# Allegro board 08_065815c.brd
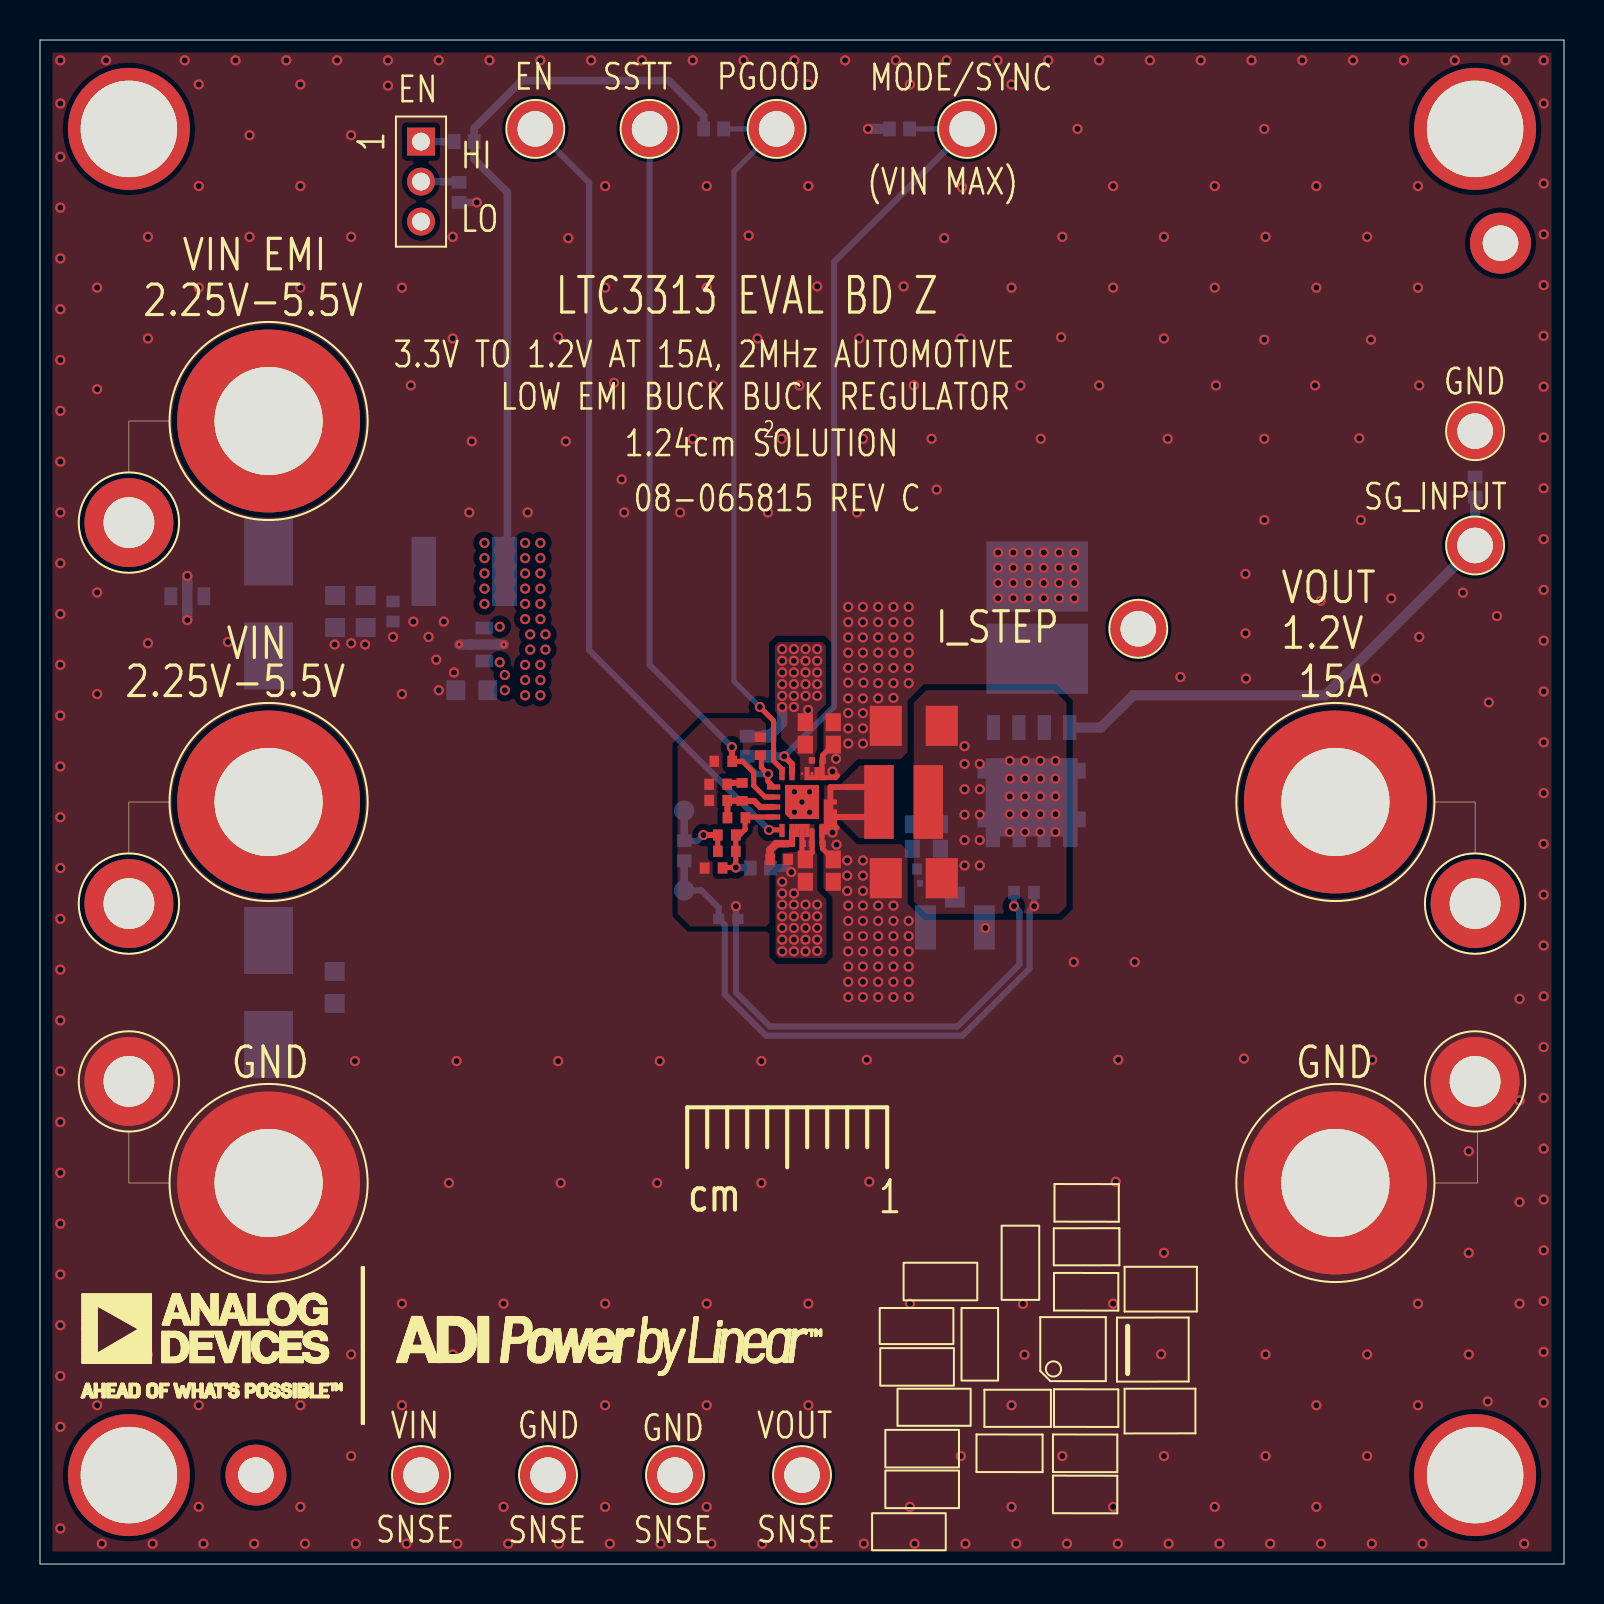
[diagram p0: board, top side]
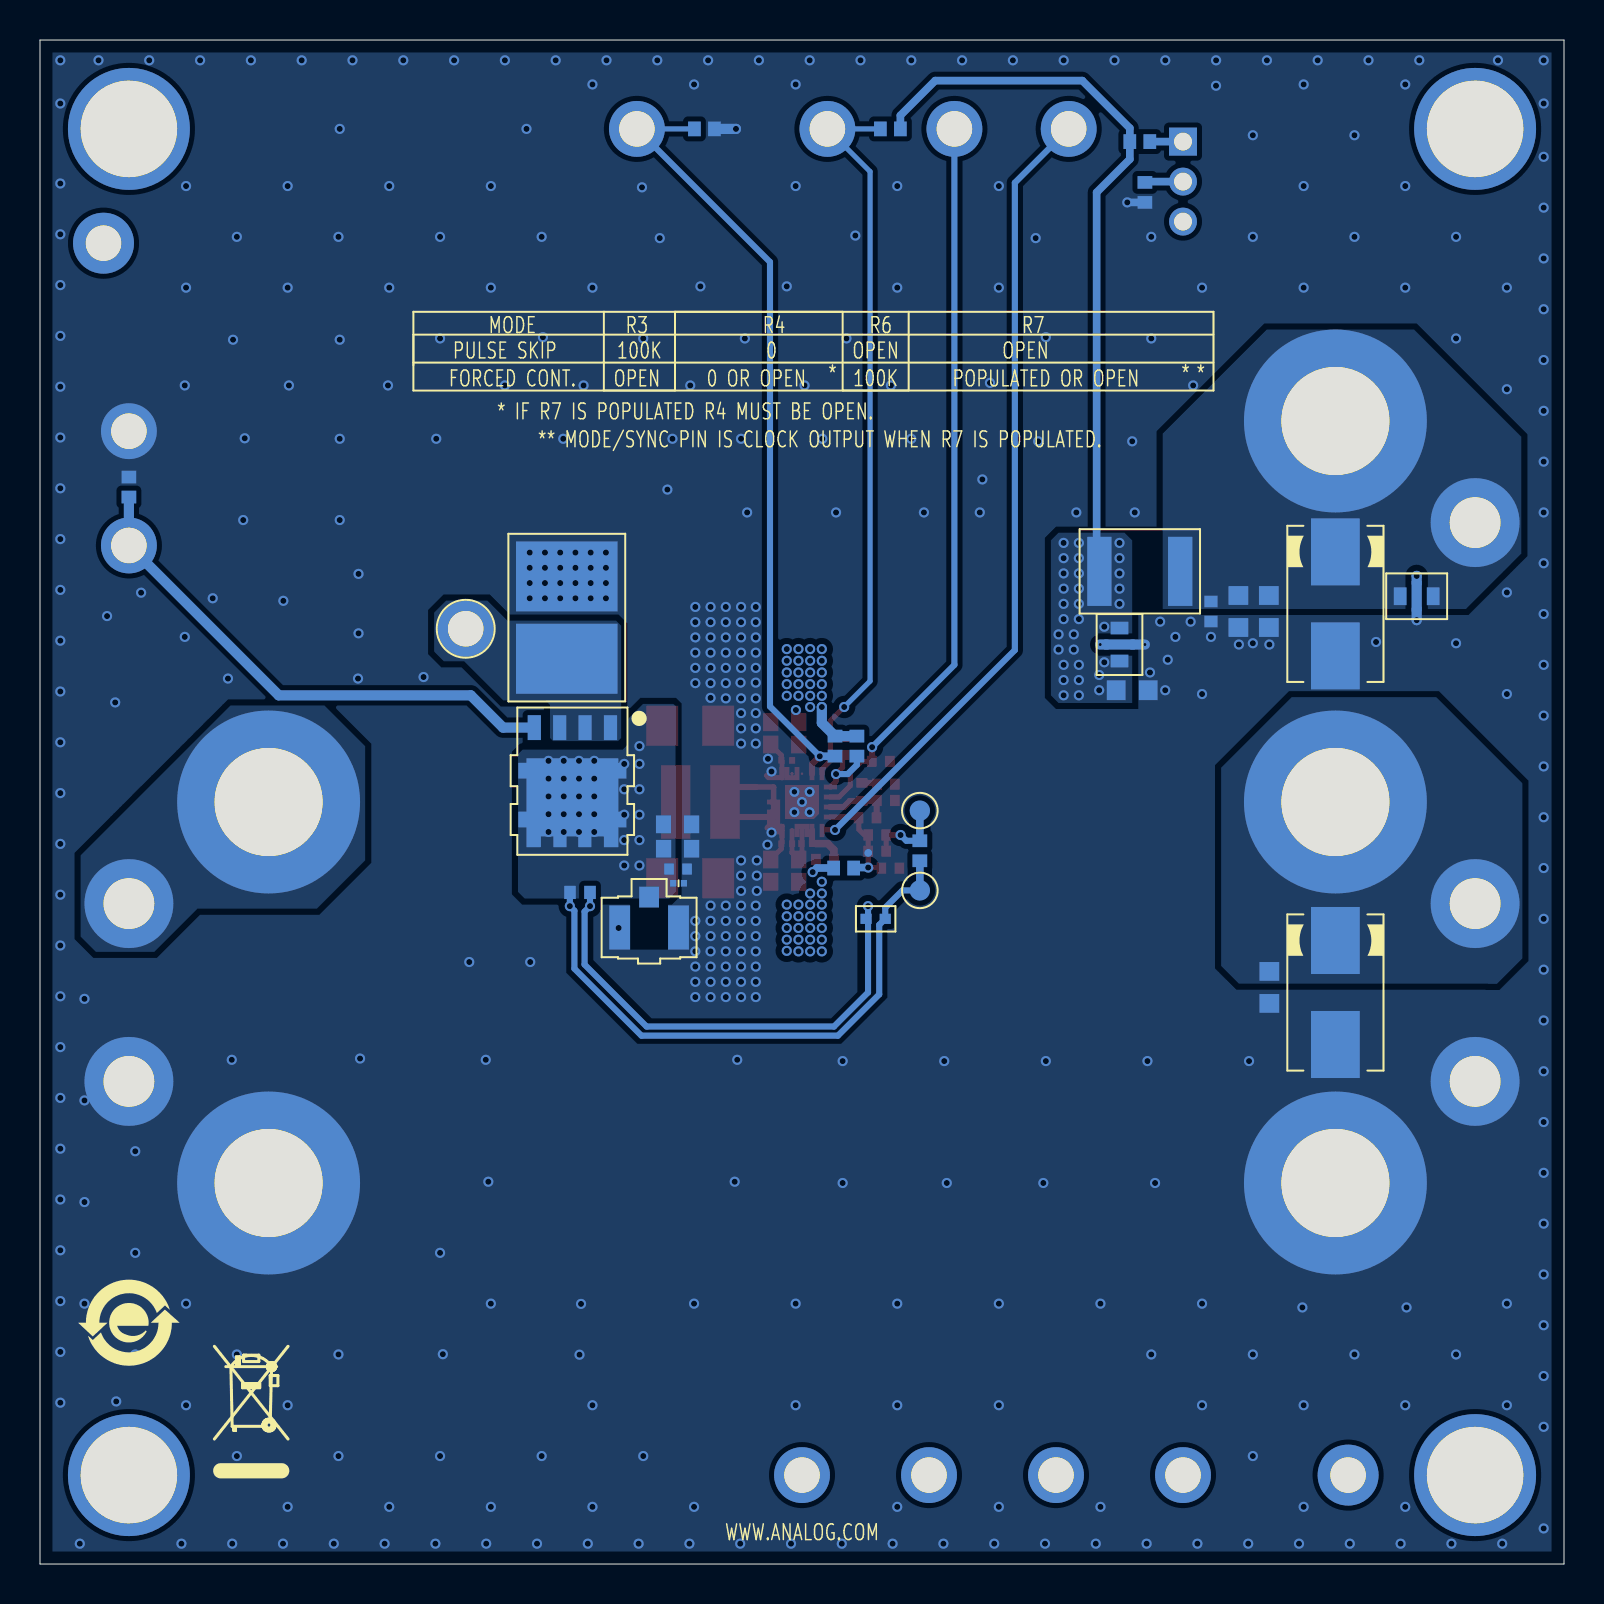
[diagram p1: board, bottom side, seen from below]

Outline 76.2 x 76.2 mm; copper layers: TOP, INTERNAL LAYER 1, INTERNAL LAYER 2, BOTTOM. Coordinates in mm from the lower left corner of the outline.
Outline path: 0,76.2 0,0 76.2,0 76.2,76.2 0,76.2

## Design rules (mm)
constraint set DEFAULT: min track width 0.203
net group SENSE LINES: nets GND_POWER

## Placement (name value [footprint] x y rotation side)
C1  470uF  [C7343-43]  11.43 28.57 270 bottom
C2  10UF  [C0603]  38.96 35.23 180 top
C3  10UF  [C0603]  38.96 40.97 180 top
C4  47pF  [C0402]  34.34 36.45 180 top
C5  47UF  [C1206H71]  43.69 41.91 0 top
C6  47UF  [C1206H71]  43.69 34.29 0 top
C7  0.1uF  [C0402]  49.2 33.58 180 bottom
C8  1UF  [C0201]  44.27 34.04 0 bottom
C9  0.033uF  [C0402]  34.16 40.13 0 top
C10  3.3pF  [C0402]  33.91 38.18 0 top
C11  0.1uF  [C0402H22]  34.42 32.26 180 bottom
C12  2.2UF  [C0402]  36.96 35.23 180 top
C13  10uF  [C0603#2]  16.28 47.62 90 bottom
C14  10uF  [C0603#2]  21.59 43.69 0 bottom
C15  0.1uF  [C0402]  17.65 47.62 90 bottom
C16  10uF  [C0603#2]  14.73 28.83 90 bottom
C17  10uF  [C0603#2]  14.76 47.62 90 bottom
C18  470uF  [C7343-43]  11.43 48.01 270 bottom
C19  1UF  [C0201]  38.86 36.02 180 top
C20  1UF  [C0201]  38.86 40.18 180 top
C21  10UF  [C0603]  38.96 34.11 180 top
C22  10UF  [C0603]  38.96 42.09 180 top
C23  0.1uF  [C0201]  37.87 36.02 0 top
C24  470pF  [C0402]  33.91 38.99 0 top
C25  0.22UF  [C0603-4P]  7.37 48.39 180 bottom
C26  0.22UF  [C0603-4P]  22.23 45.97 270 bottom
C27  10UF  [C0603]  44.32 36.98 0 bottom
C28  10UF  [C0603]  44.32 35.76 0 bottom
C29  2.2UF  [C0402]  44.3 34.75 180 bottom
J1  U.FL-R-SMT-1(01)  [CNHIROSE-U_FL-R-SMT-1]  45.75 31.83 0 bottom
JP1  62000311121  [CNTHMHDR1X3L236W79H244]  19.05 71.12 270 top
L1  0.08UH  [LSMSQ157H83]  43.18 38.1 0 top
L2  100OHM AT 100MEGHZ  [L1812H100]  21.21 49.63 0 bottom
NOREF  -  []  -6.46 -76.8 0 top
NOREF#2  -  [unnamed#2]  4.45 71.75 0 top
NOREF#3  -  []  76.2 0 90 top
NOREF#4  -  []  573.08 -141.72 0 top
NOREF#5  -  [unnamed#2]  4.45 4.45 0 top
NOREF#6  -  []  253.15 176.72 0 top
NOREF#7  -  []  76.2 76.2 180 top
NOREF#8  -  []  548.13 -131.57 0 top
NOREF#9  -  []  32.36 22.83 0 top
NOREF#10  -  []  287.87 -23.16 0 top
NOREF#11  -  []  -142.37 -122.3 0 top
NOREF#12  -  [unnamed#2]  71.75 71.75 0 top
NOREF#13  -  []  574.58 -131.56 0 top
NOREF#14  -  []  -184.91 -324.23 0 top
NOREF#15  -  []  -29.02 -64.83 0 top
NOREF#16  -  []  2.08 7.03 0 top
NOREF#17  -  []  605.28 -136.65 0 top
NOREF#18  -  []  38.1 86.36 0 top
NOREF#19  -  []  371.82 -130.71 0 top
NOREF#20  -  []  367.58 -140.87 0 top
NOREF#21  -  []  402.32 -135.81 0 top
NOREF#22  -  []  0 76.2 270 top
NOREF#23  -  [unnamed#2]  73.03 66.04 0 top
NOREF#24  -  []  76.2 0 90 top
NOREF#25  -  []  345.17 -130.73 0 top
NOREF#26  -  [unnamed#2]  71.75 4.45 0 top
NOREF#27  -  []  -114.3 -114.3 0 top
NOREF#28  -  []  -184.91 -324.23 0 top
NOREF#29  -  [unnamed#2]  10.79 4.45 0 top
NOREF#30  -  []  71.75 12.06 180 bottom
NOREF#31  -  []  65.84 4.34 180 bottom
Q1  BSC010NE2LSIATMA1  [POWERFLAT_5X6]  49.58 39.14 0 bottom
R1  1MEG  [R0402]  21.21 71.12 0 bottom
R2  249K  [R0402]  20.95 68.58 270 bottom
R3  100K  [R0402]  36.45 40.89 90 bottom
R4  0  [R0402]  35.36 40.89 90 bottom
R5  100K  [R0402]  36.02 34.8 0 bottom
R6  100K  [R0402]  42.98 71.75 0 bottom
R7  100K  [R0402]  36.02 40.89 270 top
R8  20  [R0402]  32.21 35.66 90 bottom
R9  140K  [R0402]  34.34 35.64 180 top
R10  100K  [R0402]  33.68 34.8 0 top
R11  100K  [R0402]  33.68 71.75 0 bottom
R12  4.99K  [R0402]  35.1 38.61 90 top
R13  100K  [R0402]  34.82 37.31 0 top
R14  0.02  [R2818]  49.86 47.32 270 bottom
R15  10K  [R0402]  71.75 53.85 270 bottom
TP1  2308-2-00-80-00-00-07-0  [CNMILLMAX2308]  46.35 71.75 0 top
TP2  2308-2-00-80-00-00-07-0  [CNMILLMAX2308]  71.75 56.64 0 top
TP3  2308-2-00-80-00-00-07-0  [CNMILLMAX2308]  19.05 4.45 0 top
TP4  2501-2-00-80-00-00-07-0  [CNMILLMAX2501]  4.45 33.02 0 top
TP5  2308-2-00-80-00-00-07-0  [CNMILLMAX2308]  38.1 4.45 0 top
TP6  575-4  [CNBANANAD312LD203]  11.43 38.1 0 top
TP7  2501-2-00-80-00-00-07-0  [CNMILLMAX2501]  71.75 33.02 0 top
TP8  575-4  [CNBANANAD312LD203]  64.77 38.1 0 top
TP9  575-4  [CNBANANAD312LD203]  11.43 19.05 0 top
TP10  2501-2-00-80-00-00-07-0  [CNMILLMAX2501]  4.45 24.13 0 top
TP11  575-4  [CNBANANAD312LD203]  64.77 19.05 0 top
TP12  2308-2-00-80-00-00-07-0  [CNMILLMAX2308]  25.4 4.45 0 top
TP13  2501-2-00-80-00-00-07-0  [CNMILLMAX2501]  71.75 24.13 0 top
TP14  2308-2-00-80-00-00-07-0  [CNMILLMAX2308]  31.75 4.45 0 top
TP15  2308-2-00-80-00-00-07-0  [CNMILLMAX2308]  24.77 71.75 0 top
TP16  2308-2-00-80-00-00-07-0  [CNMILLMAX2308]  30.48 71.75 0 top
TP17  2308-2-00-80-00-00-07-0  [CNMILLMAX2308]  36.83 71.75 0 top
TP18  2501-2-00-80-00-00-07-0  [CNMILLMAX2501]  4.45 52.07 0 top
TP19  575-4  [CNBANANAD312LD203]  11.43 57.15 0 top
TP20  2308-2-00-80-00-00-07-0  [CNMILLMAX2308]  71.75 50.93 0 top
TP21  2308-2-00-80-00-00-07-0  [CNMILLMAX2308]  54.91 46.76 0 top
TPA1  TESTPAD  [TPSMC40]  32.21 37.67 180 bottom
TPB1  TESTPAD  [TPSMC40]  32.21 33.68 180 bottom
U1  LTC3313EV  [QFN18_3X3_PAD1_7X1_7_RP]  38.1 38.1 0 top

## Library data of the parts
C1 C18 = CAPP: Tolerance: 20; User Part Number: UPN; alternate symbols: (); part number: CAPP_SM-470UF,6.3V,20,E041192,C7343-43; tolerance: 20
C2 C3 C21 C22 C27 C28 = CAP: User Part Number: UPN; Tolerance: 20; alternate symbols: (C0603L); part number: CAP_SM-10UF,6.3V,20,E044636,C0603; tolerance: 20
C4 = CAP: User Part Number: UPN; Tolerance: 5; alternate symbols: (C0402L); part number: CAP_SM-47PF,50V,5,E011821,C0402; tolerance: 5
C5 C6 = CAP: Tolerance: 20; User Part Number: UPN; alternate symbols: (); part number: CAP_SM-47UF,6.3V,20,E044689,C1206H71; tolerance: 20
C7 C15 = CAP: User Part Number: UPN; Tolerance: 10; alternate symbols: (C0402L); part number: CAP_SM-0.1UF,16V,10,E028141,C0402; tolerance: 10
C8 C19 C20 = CAP: Tolerance: 20; User Part Number: UPN; alternate symbols: (C0201L); part number: CAP_SM-1UF,6.3V,20,E044778,C0201; tolerance: 20
C9 = CAP: User Part Number: UPN; Tolerance: 10; alternate symbols: (C0402L); part number: CAP_SM-0.033UF,25V,10,E025701,C0402; tolerance: 10
C10 = CAP: User Part Number: UPN; Tolerance: 0.1pF; alternate symbols: (C0402L); part number: CAP_SM-3.3PF,50V,0.1PF,E041182,C0402; tolerance: 0.1pF
C11 = CAP: Tolerance: 10; User Part Number: UPN; alternate symbols: (); part number: CAP_SM-0.1UF,50V,10,E018452,C0402H22; tolerance: 10
C12 C29 = CAP: User Part Number: UPN; Tolerance: 10; alternate symbols: (C0402L); part number: CAP_SM-2.2UF,10V,10,E055500,C0402; tolerance: 10
C13 C14 C16 C17 = CAP: User Part Number: UPN; Tolerance: 20; alternate symbols: (C0603L,C0603L_ALT); part number: CAP_SM-10UF,6.3V,20,E030255,C0603; tolerance: 20
C23 = CAP: Tolerance: 10; User Part Number: UPN; alternate symbols: (C0201NC,C0201L); part number: CAP_SM-0.1UF,10V,10,E033924,C0201; tolerance: 10
C24 = CAP: User Part Number: UPN; Tolerance: 5; alternate symbols: (C0402L); part number: CAP_SM-470PF,50V,5,E021713,C0402; tolerance: 5
C25 C26 = CAP4P_V2: Tolerance: 20; User Part Number: UPN; alternate symbols: (); part number: CAP4P_V2_SM-0.22UF,6.3V,20,E043922,C0603-4P; tolerance: 20
J1 = CNBNC3P: Tolerance: N/A; User Part Number: UPN; alternate symbols: (); part number: CNBNC3P_SM-U.FL-R-SMT-1(01),E022198,CNHIROSE-U_FL-R-SMT-1; tolerance: N/A
JP1 = CN3P: User Part Number: UPN; Tolerance: N/A; alternate symbols: (); part number: CN3P_TH-62000311121,E033291,CNTHMHDR1X3L236W79H244; tolerance: N/A
L1 = IND: User Part Number: UPN; Tolerance: 20; alternate symbols: (); part number: IND_SM-0.08UH,20,E050319,LSMSQ157H83; tolerance: 20
L2 = FERRITE: User Part Number: UPN; Tolerance: 25; alternate symbols: (); part number: FERRITE_SM-100OHM AT 100MEGHZ,25,E032797,L1812H100; tolerance: 25
Q1 = TRANNMOSFET_V13: User Part Number: UPN; Tolerance: N/A; alternate symbols: (); part number: TRANNMOSFET_V13_SM-BSC010NE2LSIATMA1,E051623,POWERFLAT_5X6; tolerance: N/A
R1 = RES: User Part Number: UPN; Tolerance: 1; alternate symbols: (R0402L); part number: RES_SM-1MEG,E041482,1/16W,1,R0402; tolerance: 1
R2 = RES: User Part Number: UPN; Tolerance: 1; alternate symbols: (R0402L); part number: RES_SM-249K,E041500,1/16W,1,R0402; tolerance: 1
R3 R5-R7 R10 R13 = RES: User Part Number: UPN; Tolerance: 1; alternate symbols: (R0402L,R0402L_ALT); part number: RES_SM-100K,E003796,1/10W,1,R0402; tolerance: 1
R4 = RESJMPRSHRT: User Part Number: UPN; Tolerance: JUMPER; alternate symbols: (R0402L); part number: RESJMPRSHRT_SM-0,E003438,1/10W,JUMPER,R0402; tolerance: JUMPER
R8 = RES: User Part Number: UPN; Tolerance: 1; alternate symbols: (R0402L); part number: RES_SM-20,E020520,1/10W,1,R0402; tolerance: 1
R9 = RES: User Part Number: UPN; Tolerance: 1; alternate symbols: (R0402L); part number: RES_SM-140K,E045852,1/16W,1,R0402; tolerance: 1
R11 = RES: User Part Number: UPN; Tolerance: 5; alternate symbols: (R0402L); part number: RES_SM-100K,E027220,1/16W,5,R0402; tolerance: 5
R12 = RES: User Part Number: UPN; Tolerance: 1; alternate symbols: (R0402L); part number: RES_SM-4.99K,E006643,1/10W,1,R0402; tolerance: 1
R14 = RES: Tolerance: 1; User Part Number: UPN; alternate symbols: (); part number: RES_SM-0.02,E045144,10W,1,R2818; tolerance: 1
R15 = RES: User Part Number: UPN; Tolerance: 5; alternate symbols: (R0402L); part number: RES_SM-10K,E019640,1/16W,5,R0402; tolerance: 5
TP1-TP3 TP5 TP12 TP14-TP17 TP20 TP21 = CNTP1P: User Part Number: UPN; Tolerance: N/A; alternate symbols: (); part number: CNTP1P_TH-2308-2-00-80-00-00-07-0,E030692,CNMILLMAX2308; tolerance: N/A
TP4 TP7 TP10 TP13 TP18 = CNTP1P: User Part Number: UPN; Tolerance: N/A; alternate symbols: (); part number: CNTP1P_TH-2501-2-00-80-00-00-07-0,E031108,CNMILLMAX2501; tolerance: N/A
TP6 TP8 TP9 TP11 TP19 = CNTP1P: Tolerance: N/A; User Part Number: UPN; alternate symbols: (); part number: CNTP1P_TH-575-4,E012555,CNBANANAD312LD203; tolerance: N/A
TPA1 TPB1 = NCTESTPAD: Tolerance: N/A; User Part Number: UPN; alternate symbols: (); part number: NCTESTPAD_SM-TESTPAD,E019801,TPSMC40; tolerance: N/A
U1 = ADLTC3313: User Part Number: UPN; Tolerance: N/A; alternate symbols: (); part number: ADLTC3313_SM-LTC3313EV,E046094,QFN18_3X3_PAD1_7X1_7_RP; tolerance: N/A

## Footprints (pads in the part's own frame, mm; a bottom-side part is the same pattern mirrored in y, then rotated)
C0201
  rect 0.305x0.33 smd: 1(-0.27,0) 2(0.27,0)
C0402
  rect 0.483x0.559 smd: 1(-0.45,0) 2(0.45,0)
C0402H22
  rect 0.559x0.508 smd: 1(-0.479,0) 2(0.479,0)
C0603
  rect 0.762x0.889 smd: 1(-0.7,0) 2(0.7,0)
C0603#2
  rect 0.94x0.991 smd: 1(-0.8,0) 2(0.8,0)
C0603-4P
  rect 0.635x0.889 smd: 1(-0.826,0) 3(0.826,0)
  round 0.127 smd: 2(0,-0.635) 4(0,0.635)
C1206H71
  rect 1.6x2.007 smd: 1(-1.397,0) 2(1.397,0)
C7343-43
  rect 3.353x2.438 smd: N(2.6,0) P(-2.6,0)
CNBANANAD312LD203
  round 9.144 hole 5.41: 1(0,0)
CNHIROSE-U_FL-R-SMT-1
  rect 0.991x1.041 smd: 1(0,-1.521)
  rect 1.041x2.21 smd: 2(-1.471,0) 3(1.471,0)
CNMILLMAX2308
  round 2.794 hole 1.778: 1(0,0)
CNMILLMAX2501
  round 4.445 hole 2.54: 1(0,0)
CNTHMHDR1X3L236W79H244
  rect 1.397x1.397 hole 0.889: 1(0,0)
  round 1.397 hole 0.889: 2(2,0) 3(4,0)
L1812H100
  rect 1.219x3.454 smd: 1(-2.02,0) 2(2.02,0)
LSMSQ157H83
  rect 1.473x3.683 smd: 1(-1.232,0) 2(1.232,0)
POWERFLAT_5X6
  rect 0.66x1.245 smd: 1(-1.905,-2.678) 2(-0.635,-2.678) 3(0.635,-2.678) 4(1.905,-2.678)
  custom 1.111x1.111 smd: 5(0,1.077)
QFN18_3X3_PAD1_7X1_7_RP
  rect 0.254x0.66 smd: 1(-1,-1.425) 2(-0.5,-1.425) 5(1,-1.425) 10(1,1.42) 13(-0.5,1.42) 14(-1,1.42)
  custom 0.165x0.165 smd: 3(0,-1.425) 6(1.42,-0.75) 11(0.5,1.42)
  round 0.127 smd: 4(0.5,-1.425) 7(1.42,-0.25) 8(1.42,0.25) 9(1.42,0.75) 12(0,1.42)
  rect 0.66x0.254 smd: 15(-1.42,0.75) 16(-1.42,0.25) 17(-1.42,-0.25) 18(-1.42,-0.75)
  custom 0.425x0.425 smd: PAD(0,0)
R0402
  rect 0.483x0.559 smd: 1(-0.45,0) 2(0.45,0)
R2818
  rect 3.505x5.08 smd: 1(-2.057,0) 2(2.057,0)
TPSMC40
  round 1.016 smd: 1(0,0)
unnamed#2
  round 6.096 hole 4.826 unplated: (0,0)

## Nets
GND_POWER: C1.N(N2) C2.1 C3.1 C5.1 C6.1 C7.2(N2) C8.1 C9.1 C10.1 C11.1 C12.2(N2) C13.1 C14.1 C15.1 C16.1 C17.1 C18.N(N2) C19.1 C20.1 C21.1 C22.1 C23.1 C24.1 C25.2 C25.4(G2) C26.2 C26.4(G2) C27.1 C28.1 C29.2(N2) J1.2 J1.3(SH2) R2.2(N2) R6.1 R7.1 R10.1 R14.1 R15.1 TP2.1(N1) TP9.1(N1) TP10.1(N1) TP11.1(N1) TP12.1(N1) TP13.1(N1) TP14.1(N1) U1.2 U1.5 U1.10 U1.PAD
VIN: C1.P C2.2(N2) C3.2(N2) C12.1 C14.2(N2) C16.2(N2) C19.2(N2) C20.2(N2) C21.2(N2) C22.2(N2) C23.2(N2) C26.1 C26.3 L2.2(N2) R1.2(N2) R3.2(N2) R4.2(S2) R5.2(N2) R11.1 TP3.1(N1) TP4.1(N1) TP6.1(N1) U1.3 U1.4 U1.11 U1.12(VIN_4)
EN: JP1.2 R2.1 TP15.1(N1) U1.1
ITH: C10.2(N2) R12.1 R13.1 U1.17
MODE: R3.1 R6.2(N2) TP1.1(N1) U1.13
PGOOD: R11.2(N2) TP17.1(N1) U1.14
RT: R4.1 R7.2(N2) U1.15
SSTT: C9.2(N2) TP16.1(N1) U1.16
UNNAMED_1_ADLTC3313_I126_SW1: L1.1 U1.6 U1.7 U1.8 U1.9
UNNAMED_1_CAP_I12_N2: C13.2(N2) C15.2(N2) C17.2(N2) C18.P C25.1 C25.3 L2.1 TP18.1(N1) TP19.1(N1)
UNNAMED_1_CAP_I57_N2: C24.2(N2) R12.2(N2)
UNNAMED_1_CAP_I168_N2: C4.2(N2) R8.2(N2) R9.2(N2) TPA1.1(N1)
UNNAMED_1_CN3P_I27_N1: JP1.1 R1.1
UNNAMED_1_CNTP1P_I95_N1: Q1.1 Q1.2 Q1.3(S3) R14.2(N2) TP21.1(N1)
UNNAMED_1_CNTP1P_I139_N1: Q1.4 R15.2(N2) TP20.1(N1)
VFB: C4.1 R5.1 R9.1 R10.2(N2) R13.2(N2) U1.18
VOUT: C5.2(N2) C6.2(N2) C7.1 C8.2(N2) C11.2(N2) C27.2(N2) C28.2(N2) C29.1 J1.1 L1.2(N2) Q1.5 R8.1 TP5.1(N1) TP7.1(N1) TP8.1(N1) TPB1.1(N1)

Pads without a net: JP1 3

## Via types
v1: diameter 0.508, hole 0.305, TOP to BOTTOM, 527 vias
v2: diameter 0.381, hole 0.152, TOP to BOTTOM, 2 vias
v3: diameter 0.508, hole 0.279, TOP to BOTTOM, 5 vias

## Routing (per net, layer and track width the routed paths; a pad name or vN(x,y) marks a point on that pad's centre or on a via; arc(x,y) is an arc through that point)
GND_POWER: length 111.6
  TOP w0.254: 39.22,39.32 39.78,39.32 39.88,39.42 ; C3.1 39.13,40.44 C20.1 39.1,40.15 U1.10 ; 37.6,36.02 C23.1 ; 41.17,35.18 41.15,35.2 ; 39.85,36.8 39.78,36.88 39.1,36.88 U1.5 39.1,36.05 C19.1 39.13,35.76 C2.1 ; 39.1,39.32 39.1,39.44
  TOP w0.305: U1.2 37.6,36.02 ; C23.1 37.39,36.02 ; 39.88,35.94 39.83,35.99
  TOP w0.381: C12.2 36.51,35.71 36.81,36.02 37.39,36.02
  INTERNAL LAYER 1 w0.254: TP12.1 25.4,8.84 26.39,9.83 37.77,9.83 40.01,12.06 40.01,27.94 v1(40.41,28.35) ; TP14.1 33.83,6.53 39.47,6.53 48.95,16 48.95,32.65 v1(48.7,32.89)
  BOTTOM w0.305: C7.2 v1(48.7,32.89) 48.97,32.62 48.97,29.97 45.87,26.87 36.5,26.87 34.8,28.57 34.8,32.16 C11.1 34.8,32.36 v1(34.8,32.89)
  BOTTOM w0.381: R2.2 v1(21.84,68.08) ; 34.78,35.56 34.79,35.55
  BOTTOM w0.508: v2(20.95,45.97) C26.4 ; v1(7.37,49.4) C25.4 ; v2(23.19,45.97) C26.2 ; v1(7.37,47.19) C25.2 ; R6.1 v1(41.4,71.75)
  vias: v1(1.02,75.18) v1(1.02,73.03) v1(1.02,70.36) v1(1.02,67.82) v1(1.02,65.28) v1(1.02,62.74) v1(1.02,60.2) v1(1.02,57.66) v1(1.02,55.12) v1(1.02,52.58) v1(1.02,50.04) v1(1.02,47.5) v1(1.02,44.96) v1(1.02,42.42) v1(1.02,39.88) v1(1.02,37.34) v1(1.02,34.8) v1(1.02,32.26) v1(1.02,29.72) v1(1.02,27.18) v1(1.02,24.64) v1(1.02,22.1) v1(1.02,19.56) v1(1.02,17.02) v1(1.02,14.48) v1(1.02,11.94) v1(1.02,9.4) v1(1.02,6.86) v1(1.02,1.78) v1(2.86,63.82) v1(2.86,58.74) v1(2.86,48.58) v1(2.86,43.5) v1(2.86,13.02) v1(2.86,7.94) v1(3.09,1.02) v1(3.3,75.18) v1(5.4,66.36) v1(5.4,61.28) v1(5.4,46.04) v1(5.4,10.48) v1(5.63,1.02) v1(7.24,75.18) v1(7.94,73.98) v1(7.94,68.9) v1(7.94,63.82) v1(7.87,12.83) v1(7.94,7.94) v1(7.94,2.86) v1(8.17,1.02) v1(9.4,46.1) v1(9.78,75.18) v1(10.48,71.44) v1(10.48,66.36) v1(10.48,10.48) v1(10.71,1.02) v1(12.32,75.18) v1(13.02,73.98) v1(13.02,68.9) v1(13.02,63.82) v1(13.02,7.94) v1(13.02,2.86) v1(13.08,12.83) v1(13.25,1.02) v1(14.73,45.97) v1(14.86,75.18) v1(15.56,71.44) v1(15.56,66.36) v1(15.56,46.04) v1(15.56,10.48) v1(15.56,5.4) v1(15.75,25.15) v1(15.79,1.02) v1(16.26,45.97) v1(17.4,75.18) v1(17.4,73.91) v1(17.65,46.35) v1(18.1,63.82) v1(18.1,43.5) v1(18.1,13.02) v1(18.1,7.94) v1(18.33,1.02) v1(18.54,58.93) v1(18.67,47.12) v1(19.43,46.35) v1(19.81,45.21) v1(19.94,75.18) v1(19.94,43.69) v1(20.19,47.12) v1(20.45,19.05) v1(20.64,66.36) v1(20.64,61.28) v1(20.64,10.48) v1(20.7,44.58) v1(20.83,25.15) v1(20.87,1.02) v1(21.46,52.58) v1(21.59,56.13) v1(22.48,75.18) v1(23.18,13.02) v1(23.18,2.86) v1(23.41,1.02) v1(24.38,52.58) v1(25.02,75.18) v1(25.91,61.34) v1(25.91,25.15) v1(25.95,1.02) v1(26.04,19.05) v1(26.29,56.13) v1(26.42,66.29) v1(27.56,75.18) v1(28.26,68.9) v1(28.26,63.82) v1(28.26,13.02) v1(28.26,7.94) v1(28.26,2.86) v1(28.49,1.02) v1(28.7,59.05) v1(29.08,54.23) v1(29.21,52.58) v1(30.1,75.18) v1(30.86,19.05) v1(30.99,25.15) v1(31.03,1.02) v1(32,52.58) v1(32.64,75.18) v1(32.64,56.26) v1(33.34,68.9) v1(33.34,63.82) v1(33.34,13.02) v1(33.34,7.94) v1(33.34,2.86) v1(33.57,1.02) v1(33.66,58.93) v1(35.18,75.18) v1(35.43,66.42) v1(35.88,61.28) v1(36.07,25.15) v1(36.07,19.05) v1(36.11,1.02) v1(36.4,52.58) v1(37.08,56.26) v1(37.72,75.18) v1(37.97,58.93) v1(38.42,73.98) v1(38.42,68.9) v1(38.42,13.02) v1(38.42,7.94) v1(38.65,1.02) v1(38.86,63.88) v1(39.62,39.62) v1(39.62,36.58) v1(39.8,40.26) v1(39.83,35.97) v1(40.26,75.18) v1(40.41,47.85) v1(40.41,47.09) v1(40.41,46.33) v1(40.41,45.57) v1(40.41,44.81) v1(40.41,44.07) v1(40.41,43.28) v1(40.41,42.55) v1(40.41,41.78) v1(40.41,41.02) v1(40.36,35.18) v1(40.36,34.42) v1(40.36,33.66) v1(40.41,32.92) v1(40.41,32.16) v1(40.41,31.39) v1(40.41,30.63) v1(40.41,29.87) v1(40.41,29.11) v1(40.84,52.58) v1(40.96,61.28) v1(41.15,56.26) v1(41.15,47.85) v1(41.15,47.09) v1(41.15,46.33) v1(41.15,45.57) v1(41.15,44.81) v1(41.15,43.28) v1(41.15,42.55) v1(41.15,41.78) v1(41.15,41.02) v1(41.15,35.18) v1(41.15,34.42) v1(41.15,33.66) v1(41.15,32.92) v1(41.15,32.16) v1(41.15,31.39) v1(41.15,30.63) v1(41.15,29.87) v1(41.15,29.11) v1(41.15,28.35) v1(41.17,44.07) v1(41.19,1.02) v1(41.34,25.21) v1(41.47,19.11) v1(41.91,47.85) v1(41.91,47.09) v1(41.91,46.33) v1(41.91,45.57) v1(41.91,44.81) v1(41.91,44.04) v1(41.91,43.28) v1(41.91,32.92) v1(41.91,32.16) v1(41.91,31.39) v1(41.91,30.63) v1(41.91,29.87) v1(41.91,29.11) v1(41.91,28.35) v1(42.67,47.85) v1(42.67,47.09) v1(42.67,46.33) v1(42.67,45.57) v1(42.67,44.81) v1(42.67,44.04) v1(42.67,43.31) v1(42.67,32.92) v1(42.67,32.16) v1(42.67,31.39) v1(42.67,30.63) v1(42.67,29.87) v1(42.67,29.11) v1(42.67,28.35) v1(42.8,75.18) v1(43.18,63.88) v1(43.43,47.85) v1(43.43,47.09) v1(43.43,46.33) v1(43.43,45.57) v1(43.43,44.81) v1(43.43,44.04) v1(43.43,32.16) v1(43.43,31.39) v1(43.43,30.63) v1(43.43,29.87) v1(43.43,29.11) v1(43.43,28.35) v1(43.5,73.98) v1(43.5,13.02) v1(43.5,2.86) v1(43.69,58.93) v1(43.73,1.02) v1(44.58,56.26) v1(44.83,53.72) v1(45.21,66.29) v1(45.34,75.18) v1(46.04,61.28) v1(46.04,5.4) v1(46.1,68.83) v1(46.27,1.02) v1(47.27,31.8) v1(47.88,75.18) v1(47.9,50.57) v1(47.9,49.81) v1(47.9,49.05) v1(47.9,48.29) v1(48.58,73.98) v1(48.58,63.82) v1(48.58,7.94) v1(48.58,2.86) v1(48.67,50.57) v1(48.67,49.81) v1(48.67,49.05) v1(48.67,48.29) v1(48.81,1.02) v1(49.02,58.93) v1(49.15,13) v1(49.23,10.46) v1(49.43,50.57) v1(49.43,49.81) v1(49.43,49.05) v1(49.43,48.29) v1(50.04,56.26) v1(50.19,50.57) v1(50.19,49.81) v1(50.19,49.05) v1(50.19,48.29) v1(50.42,75.18) v1(50.95,50.57) v1(50.95,49.81) v1(50.95,49.05) v1(50.95,48.29) v1(51.12,66.36) v1(51.05,61.34) v1(51.12,5.4) v1(51.35,1.02) v1(51.71,50.57) v1(51.71,49.81) v1(51.71,49.05) v1(51.71,48.29) v1(51.69,30.1) v1(51.88,71.75) v1(52.96,75.18) v1(52.96,58.93) v1(53.66,68.9) v1(53.66,63.82) v1(53.66,13.02) v1(53.66,2.86) v1(53.78,19.11) v1(53.91,25.21) v1(53.89,1.02) v1(54.74,30.1) v1(55.5,75.18) v1(56.06,10.49) v1(56.2,66.36) v1(56.2,61.28) v1(56.2,15.56) v1(56.2,5.4) v1(56.39,56.26) v1(56.43,1.02) v1(57.02,44.35) v1(58.04,75.18) v1(58.74,68.9) v1(58.74,63.82) v1(58.74,2.86) v1(58.8,58.93) v1(58.97,1.02) v1(60.2,25.27) v1(60.27,49.5) v1(60.27,46.53) v1(60.3,44.27) v1(60.58,75.18) v1(61.21,71.75) v1(61.21,61.21) v1(61.21,56.26) v1(61.21,52.2) v1(61.28,66.36) v1(61.28,10.48) v1(61.28,5.4) v1(61.51,1.02) v1(63.12,75.18) v1(63.82,68.9) v1(63.82,63.82) v1(63.75,58.93) v1(63.82,7.94) v1(63.82,2.86) v1(64.03,48.16) v1(64.05,1.02) v1(65.66,75.18) v1(65.96,56.29) v1(66.04,52.2) v1(66.36,66.36) v1(66.36,10.48) v1(66.36,5.4) v1(66.55,61.21) v1(66.61,25.21) v1(66.59,1.02) v1(66.8,44.27) v1(67.56,48.29) v1(68.2,75.18) v1(68.9,68.9) v1(68.9,63.82) v1(68.9,13.02) v1(68.9,7.94) v1(68.96,58.93) v1(68.96,46.35) v1(69.13,1.02) v1(70.74,75.18) v1(71.15,48.56) v1(71.44,20.64) v1(71.44,15.56) v1(71.44,10.48) v1(72.44,43.08) v1(72.39,8.13) v1(72.85,47.4) v1(73.28,75.18) v1(73.98,28.26) v1(73.98,23.18) v1(73.98,18.1) v1(73.98,13.02) v1(74.21,1.02) v1(75.18,75.18) v1(75.18,73.03) v1(75.18,69.03) v1(75.18,66.49) v1(75.18,63.95) v1(75.18,61.41) v1(75.18,58.87) v1(75.18,56.33) v1(75.18,53.79) v1(75.18,51.25) v1(75.18,48.71) v1(75.18,46.17) v1(75.18,43.63) v1(75.18,41.09) v1(75.18,38.55) v1(75.18,36.01) v1(75.18,33.47) v1(75.18,30.93) v1(75.18,28.39) v1(75.18,25.85) v1(75.18,23.31) v1(75.18,20.77) v1(75.18,18.23) v1(75.18,15.69) v1(75.18,13.15) v1(75.18,10.61) v1(75.18,8.07) v3(37.72,38.61) v3(37.72,37.59) v3(38.1,38.1) v3(38.48,38.61) v3(38.48,37.59)
VIN: length 87
  TOP w0.254: U1.4 38.6,35.57 C2.2 38.1,35.39 U1.3
  INTERNAL LAYER 1 w0.254: 38.94,31.45 39.09,31.29 39.12,31.29 39.55,30.86 39.55,12.29 37.54,10.29 24.89,10.29 TP3.1
  BOTTOM w0.381: R5.2 37.36,34.8 v1(37.57,34.59) ; R11.1 33.18,72.43 31.44,74.17 24.08,74.17 21.71,71.79 R1.2 21.71,70.24 23.37,68.58 23.37,49.77 L2.2
  BOTTOM w0.508: R4.2 R3.2 37.11,42.05 v1(37.11,42.85)
  vias: v1(22.23,51.05) v1(22.23,50.29) v1(22.23,49.53) v1(22.23,48.77) v1(22.23,48.01) v1(22.99,46.86) v1(22.99,45.09) v1(23.24,44.45) v1(23.24,43.69) v1(24.26,51.05) v1(24.26,50.29) v1(24.26,49.53) v1(24.26,48.77) v1(24.26,48.01) v1(24.26,47.24) v1(24.26,44.96) v1(24.26,44.2) v1(24.26,43.43) v1(24.51,46.48) v1(24.51,45.72) v1(25.02,51.05) v1(25.02,50.29) v1(25.02,49.53) v1(25.02,48.77) v1(25.02,48.01) v1(25.02,47.24) v1(25.02,44.96) v1(25.02,44.2) v1(25.02,43.43) v1(25.27,46.48) v1(25.27,45.72) v1(37.11,45.75) v1(37.11,45.16) v1(37.11,44.58) v1(37.11,43.99) v1(37.11,43.41) v1(37.11,34.11) v1(37.11,33.53) v1(37.11,32.97) v1(37.11,32.38) v1(37.11,31.8) v1(37.11,31.22) v1(37.11,30.63) v1(37.69,45.75) v1(37.69,45.16) v1(37.69,44.58) v1(37.69,43.99) v1(37.69,43.41) v1(37.69,42.85) v1(37.69,33.53) v1(37.69,32.97) v1(37.69,32.38) v1(37.69,31.8) v1(37.69,31.22) v1(37.69,30.63) v1(38.28,45.75) v1(38.28,45.16) v1(38.28,44.58) v1(38.28,43.99) v1(38.28,43.41) v1(38.28,32.97) v1(38.28,32.38) v1(38.28,31.8) v1(38.28,31.22) v1(38.28,30.63) v1(38.4,42.7) v1(38.86,45.75) v1(38.86,45.16) v1(38.86,44.58) v1(38.86,43.99) v1(38.86,43.41) v1(38.86,32.97) v1(38.86,32.38) v1(38.86,31.8) v1(38.86,31.22) v1(38.86,30.66)
EN: length 49.3
  TOP w0.203: 37.07,36.7 U1.1
  TOP w0.254: v1(36.45,36.7) 37.07,36.7
  INTERNAL LAYER 2 w0.305: TP15.1 22.13,69.12 JP1.2
  BOTTOM w0.254: 20.92,69.12 R2.1
  BOTTOM w0.305: v1(36.45,36.7) 27.46,45.69 27.46,69.06 TP15.1
  BOTTOM w0.381: JP1.2 20.92,69.12
ITH: length 3.3
  TOP w0.305: U1.17 36.01,37.85 35.71,38.15 35.11,38.15 R12.1 34.38,38.16 34.37,38.16 ; 34.37,38.16 C10.2 ; 34.37,38.16 R13.1
MODE: length 39.8
  TOP w0.305: U1.13 37.6,40 v1(37.21,40.39)
  BOTTOM w0.254: R6.2 TP1.1
  BOTTOM w0.305: 36.46,40.39 R3.1 ; 37.24,40.41 39.7,42.88 39.7,65.1 TP1.1 ; 37.2,40.39 v1(37.21,40.39)
  BOTTOM w0.381: v1(37.21,40.39) 36.46,40.39 ; 37.2,40.39 37.22,40.39 37.24,40.41
PGOOD: length 36.8
  TOP w0.254: v1(35.99,42.85) 36.68,42.16 36.68,40.16 37.1,39.73 U1.14
  BOTTOM w0.254: R11.2 TP17.1 34.7,69.62 34.7,44.15 v1(35.99,42.85)
RT: length 3.5
  TOP w0.254: R7.2 36.07,40.39 36.07,39.83 v1(36.4,39.5) 36.4,39.13 U1.15
  BOTTOM w0.305: R4.1 35.36,39.95 35.81,39.5 v1(36.4,39.5)
SSTT: length 36.5
  TOP w0.254: U1.16 36.25,38.35 35.69,38.91 35.69,39.57 35.13,40.13 C9.2
  TOP w0.305: C9.2 34.59,40.15 v1(34.59,40.84)
  BOTTOM w0.305: TP16.1 30.48,44.96 v1(34.59,40.84)
UNNAMED_1_ADLTC3313_I126_SW1: length 7.5
  TOP w0.279: U1.6 U1.9 40.4,38.85 ; 40.21,37.36 40.19,37.35
  TOP w0.305: U1.6 41.58,37.35 41.95,37.72 L1.1 41.95,38.55 41.64,38.85 40.4,38.85
UNNAMED_1_CAP_I57_N2: length 0.8
  TOP w0.305: C24.2 34.43,39.06 R12.2
UNNAMED_1_CAP_I168_N2: length 4.1
  TOP w0.254: R9.2 C4.2
  TOP w0.305: C4.2 v1(33.17,36.45)
  BOTTOM w0.305: R8.2 32.89,36.16 v1(33.17,36.45)
  BOTTOM w0.381: R8.2 TPA1.1
UNNAMED_1_CN3P_I27_N1: length 1.7
  BOTTOM w0.381: R1.1 JP1.1
UNNAMED_1_CNTP1P_I139_N1: length 26.5
  BOTTOM w0.508: R15.2 TP20.1 64.26,43.43 54.66,43.43 53.05,41.82 Q1.4
VFB: length 5.7
  TOP w0.254: v1(34.79,34.82) R9.1 C4.1 34.98,36.45 35.26,36.73 35.26,37.29 R13.2 35.31,37.35 U1.18 ; v1(34.79,34.82) 34.16,34.82 R10.2 ; v1(34.79,34.82) 34.77,34.8
  BOTTOM w0.381: R5.1 35.49,34.82 v1(34.79,34.82)
VOUT: length 62.7
  INTERNAL LAYER 1 w0.254: TP5.1 49.45,15.8 49.45,32.64 v1(49.71,32.89)
  BOTTOM w0.305: TPB1.1 33.07,33.68 33.94,32.82 C11.2 34.24,31.96 34.24,28.48 36.3,26.42 46.13,26.42 49.48,29.77 49.48,32.66 v1(49.71,32.89) 49.71,33.39 C7.1
  BOTTOM w0.381: TPB1.1 R8.1
  vias: v1(46.23,40.89) v1(46.23,40.01) v1(46.23,38.73) v1(46.23,37.47) v1(46.23,36.2) v1(46.23,34.92) v1(46.99,40.01) v1(46.99,38.73) v1(46.99,37.47) v1(46.99,36.2) v1(46.99,34.92) v1(48.49,40.16) v1(48.49,39.27) v1(48.49,38.38) v1(48.49,37.49) v1(48.49,36.6) v1(49.25,40.16) v1(49.25,39.27) v1(49.25,38.38) v1(49.25,37.49) v1(49.25,36.6) v1(50.01,40.16) v1(50.01,39.27) v1(50.01,38.38) v1(50.01,37.49) v1(50.01,36.6) v1(50.77,40.16) v1(50.77,39.27) v1(50.77,38.38) v1(50.77,37.49) v1(50.77,36.6)

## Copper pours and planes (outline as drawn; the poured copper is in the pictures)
GND_POWER on TOP, BOTTOM, INTERNAL LAYER 2: 0.62,75.58 75.58,75.58 75.58,0.62 0.62,0.62
GND_POWER on INTERNAL LAYER 1: 0.64,75.56 75.56,75.56 75.56,0.64 0.64,0.64
VIN on TOP: 38.86,36.09 38.86,33.68 39.32,33.22 39.32,30.48 39.14,30.3 36.96,30.3 36.78,30.48 36.78,34.49 37.08,34.8 37.08,35.51 37.16,35.59 37.54,35.59 37.93,35.98 37.95,35.98 37.97,36 37.97,37.01 38.73,37.01 38.73,36.22
VIN on TOP: 38,39.19 38.73,39.19 38.73,39.95 38.86,40.08 38.86,42.55 39.29,42.98 39.29,45.92 39.12,46.1 36.93,46.1 36.75,45.92 36.75,42.62 37.05,42.33 37.05,41.3 38,40.35
VIN on BOTTOM: 21.59,43.05 21.59,51.18 21.97,51.56 25.27,51.56 25.65,51.18 25.65,43.43 25.27,43.05
VIN on BOTTOM: 6.38,43.34 13.62,43.34 17.14,39.81 17.14,29.91 16.26,29.02 3.81,29.02 3.8,29.01 3.35,29.01 2.08,30.28 2.08,39.04
VIN on INTERNAL LAYER 1: 7.49,51.56 2.79,46.86 2.79,31.37 7.49,26.67 38.91,26.67 39.27,27.03 39.27,33.96 38.68,34.54 32.54,34.54 31.88,35.2 31.88,41.02 33.15,42.29 38.86,42.29 39.19,42.62 39.19,51.31 38.94,51.56
UNNAMED_1_ADLTC3313_I126_SW1 on TOP: 39.19,38.99 40.06,38.99 41,39.93 41.66,39.93 41.66,36.3 40.97,36.3 40.06,37.21 39.19,37.21
UNNAMED_1_CAP_I12_N2 on BOTTOM: 20.07,47.75 20.07,56.52 14.86,61.72 7.49,61.72 2.13,56.36 2.13,50.52 4.9,47.75
UNNAMED_1_CNTP1P_I95_N1 on BOTTOM: 47.14,46.91 47.4,47.17 52.83,47.17 53.84,48.17 55.89,48.17 56.49,47.57 56.49,45.62 56.01,45.14 54.99,45.14 53.04,43.18 50.93,43.18 50.7,42.95 50.7,41.3 50.55,41.15 47.29,41.15 47.14,41.3
VOUT on TOP: 44.32,43.69 43.69,43.05 43.69,33.15 44.32,32.51 50.95,32.51 51.33,32.89 51.33,43.05 50.7,43.69
VOUT on BOTTOM: 44.42,42.9 44.42,33.58 44.73,33.27 51.97,33.27 52.3,33.6 52.3,40.49 52.07,40.72 47.07,40.72 46.79,41 46.79,42.27 46.05,43 44.53,43
VOUT on BOTTOM: 66.67,42.93 74.17,35.43 74.17,31.37 73.41,30.61 70.48,30.61 68.33,32.77 62.36,32.77 59.94,35.18 59.94,40.89 61.98,42.93
VOUT on INTERNAL LAYER 1: 74.17,39.98 74.17,31.88 68.45,26.16 45.85,26.16 44.78,27.23 44.78,42.88 45.42,43.51 70.64,43.51

Small or netless copper shapes (teardrops, artwork), in the pictures only: 3 on BOTTOM

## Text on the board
Ref Des/Silkscreen Bottom: * | POPULATED OR OPEN | R7 | OPEN | R6 | 100K | ** MODE/SYNC PIN IS CLOCK OUTPUT WHEN R7 IS POPULATED. | WWW.ANALOG.COM | R4 | 0 | 0 OR OPEN | * IF R7 IS POPULATED R4 MUST BE OPEN. | R3 | MODE | FORCED CONT. | PULSE SKIP
User.Comments: DETAIL "C" | DETAIL "B" | DETAIL "A" | (4X) | 2.    WORKMANSHIP SHALL BE IN ACCORDANCE WITH IPC-A-610 | 1.    BOARD ACCEPTABILITY PER ANALOG DEVICES, INC. SPECIFICATION | TST00119 (LATEST REVISION). | 6.    INSTALL SHUNTS AS SHOWN ON ASSY DRAWING. | 7.    DEPANELIZE BOARDS AFTER ASSEMBLY AND ROUTE-OUT THE BREAKOUT | 8.    INSTALL TURRETS, STAND-OFFS AS SHOWN BELOW: | 3.    REPAIRS PER IPC-7711/21(LATEST REVISION) ARE ALLOWED. | 4.    REPAIRS ARE NOT ALLOWED IN SOLDERMASK FREE AREAS ON EITHER | 5.    PARTS TO OMIT WILL BE SPECIFIED ON THE BILL OF MATERIALS | ASSEMBLY NOTES: UNLESS OTHERWISE SPECIFIED | TABS ON FOUR SIDES OF THE BOARD EDGE. | SIDE OF THE BOARD. | LOCATIONS OF OMITTED PARTS SHALL BE FREE OF SOLDER. | MASK THE SOLDER STENCIL WHERE SMT PARTS ARE OMITTED. | TOP ASSEMBLY | BOTTOM ASSEMBLY | MIRROR VIEW
Ref Des/Silkscreen Top: 2 | SNSE | VIN | 3.3V TO 1.2V AT 15A, 2MHz AUTOMOTIVE | EN | HI | LO | LOW EMI BUCK BUCK REGULATOR | GND | SSTT | 1.24cm SOLUTION | PGOOD | VOUT | (VIN MAX) | MODE/SYNC | SG_INPUT | 2.25V-5.5V | VIN EMI | I_STEP | 1.2V | 15A | LTC3313 EVAL BD Z
DIMENSION: -.175 | "0" | -.425 | 2.575
PAGE_OUTLINE: LTC3313-EBZ
User.15: .0028" | .0005" | .012" | .028" | PREPREG | CORE MATERIAL | NONE REQUIRED | 16.    PRODUCTION BOARDS TO BE PANELIZED AND SHIPPED INTACT. | PROTOTYPE BOARDS ARE SHIPPED AS SINGLE PCS. | SOLDER SAMPLE REQUIRED. | 15.    TENT VIAS BOTH SIDES.
User.17: L2 POWER/GROUND | 08-      -07
User.18: L3 GROUND | 08-      -08
User.45: FIGURE | SIZE | 6.0 | 11.0 | 12.0 | 35.0 | 70.0 | 100.0 | 213.0 | 190.0 | PLATED | NON-PLATED | FINISHED HOLES IN MILS | ALL UNITS ARE IN MILS | QTY | 2 | 5 | 514 | 3 | 11 | 4 | TOLERANCE/NOTES | (10 PLCS) : MILL-MAX 2308 | (6 PLCS) : MILL-MAX 2501 | (5 PLCS) : KEYSTONE 575-4
